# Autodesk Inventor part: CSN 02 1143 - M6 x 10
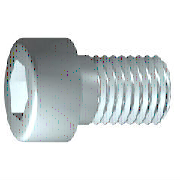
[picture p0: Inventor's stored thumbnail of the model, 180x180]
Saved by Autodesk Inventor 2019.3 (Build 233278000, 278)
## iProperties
Created: 2018-01
Part Number: CSN 02 1143 - M6 x 10
Material: Ocel, měkká
Description: Šrouby s válcovou hlavou s vnitřním šestihranem
Document SubType Name: Modeling
Standard: CSN 02 1143
Designer: B-hon
Standards Organization: CSN
Language: cs-CZ
Size Designation: M6 x 10
Categories: <MemberInstance><Categories><Category DisplayName="Spojovací materiál" InternalName="e4da775c-781d-43d5-af7c-5136215cf5a6" Mnemonic="FSTN"><Category DisplayName
Density: 7.85 g/cm^3
Appearance: Pololeštěná
IsCustomPart: 0
Author: B-hon
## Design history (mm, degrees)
sketch "Náčrt1"
  geometry: L1 (-1.033, 0)-(10, 0); L2 (10, 0)-(10, 3); L3 (10, 3)-(3, 3); L4 (3, 3)-(2.386, 3); L5 (2.386, 3)-(0, 3); L6 (0, 3)-(0, 5); L7 (0, 5)-(-6, 5); L8 (-6, 5)-(-6, 2.887); L9 (-6, 2.887)-(-2.7, 2.887); L10 (-2.7, 2.887)-(-1.033, 0); L11 (-9.2, 0)-(13.2, 0) reference; L12 (0, -1)-(0, 6) reference; L13 (3, 3)-(0, 3)
  constraints: 22 end point, 6 parallel, 2 collinear, 2 perpendicular, 1 horizontal, 1 point on line
  dimensions: "d1" = 7 distance from line of L3.end L2 (= GEL); "d2" = 0.61355 distance of L4.end L3.end (computed from GAL); "d3" = 6 distance between parallel lines of L8 L6 (= KOH); "d4" = 3.3 distance of L8.end L9.end (= INTI); "d5" = 60 deg angle of L10 L1; "d6" = 6 diameter of L3 L1 (= GD); "d7" = 6 diameter of L5 L1 (= BDM); "d8" = 5.7735 diameter of L9 L1 (= 1.1547 x SW); "d9" = 10 diameter of L7 L1 (= KOD); "d26" = 10 distance between parallel lines of L12 L2 (= NLG)
revolve "Těleso" sketch "Náčrt1" stored, may be unused: angle "d10" = 90 deg
sketch "Náčrt2"
  geometry: L1 (0, -7)-(0, 7) reference; L2 (-7, 0)-(7, 0) reference; L3 (2.887, 0)-(1.443, -2.5); L4 (1.443, -2.5)-(-1.443, -2.5); L5 (-1.443, -2.5)-(-2.887, 0); L6 (-2.887, 0)-(-1.443, 2.5); L7 (-1.443, 2.5)-(1.443, 2.5); L8 (1.443, 2.5)-(2.887, 0); 2 further points
  constraints: 12 end point, 1 coincident, 1 horizontal alignment, 1 point on line, 12 other
extrude "Drážka" join sketch "Náčrt2" stored distance "d11" = 10; taper "d12" = 0 deg
workplane "Work Plane1"
fillet "Fillet2" dims "d30" = 0.1 (= R)
body "Solid1"
fillet "Zaoblení1" dims "d17" = 0.5 (= RR)
feature "Závit" dims "d13" = 7 (= GEL), "d14" = 0
chamfer "Zkosení1" distance "d15" = 0.61345 (= -0.5 x SPD + 0.5 x GD); stored, may be unused: second distance "d16" = 0.61345 (= GUL), angle "d27" = 45 deg
other parameters: "GD" = 6 (= NND) [user parameter; used in 2 equation terms], "NLG" = 10 [user parameter; used in 1 equation term], "GEL" = 7 [user parameter; used in 2 equation terms], "KOD" = 10 [user parameter; used in 1 equation term], "KOH" = 6 (= NND) [user parameter; used in 1 equation term], "INTI" = 3.3 [user parameter; used in 1 equation term], "GAL" = 0.61345 (= 0.61345 x PTC) [user parameter; used in 1 equation term], "GUL" = 0.61345 (= 0.61345 x PTC) [user parameter; used in 1 equation term], "BDM" = 6 (= NND) [user parameter; used in 1 equation term], "SW" = 5 [user parameter; used in 2 equation terms], "RR" = 0.5 [user parameter; used in 1 equation term], "SPD" = 4.7731 (= NND - 1.2269 x PTC) [user parameter; used in 1 equation term], "d19" = 0, "d28" = 0, "d29" = 0, "R" = 0.1 [user parameter; used in 1 equation term], "TOA" = 30 deg [user parameter], "GD1" = 4.7731 (= THREADDIA - 1.2269 x PTC) [user parameter], "THREADDIA" = 6 [user parameter; used in 1 equation term], "FAWI" = 45 deg [user parameter], "PTC" = 1 [user parameter; used in 5 equation terms], "NND" = 6 [user parameter; used in 4 equation terms], "E0" = 5.775 (= 1.155 x SW) [user parameter], "PHH" = 0 [user parameter]
